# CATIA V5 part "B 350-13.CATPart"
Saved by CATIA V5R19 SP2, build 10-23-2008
Part number: B 350-13
Bounding box of the stored display mesh (mm): x -15.868 to 15.868, y -15.868 to 15.868, z 0 to 75.4
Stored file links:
  C:\Users\Bora\Desktop\3D Katı model\B serisi\B 350\B 350-13.CATPart
  C:\Program Files\Dassault Systemes\B19\intel_a\reffiles\standard\MetricThickPitch.txt
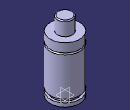
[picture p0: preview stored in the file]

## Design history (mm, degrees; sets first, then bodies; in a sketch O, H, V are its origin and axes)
Body1 (main body)
  Sketch1 on yz-plane, origin (0, 0, 0), H (0, 1, 0), V (0, 0, 1)
    point P3 (8, 74.4)
    point P5 (8, 74.4)
    point P7 (16, 50.9)
    point P8 (16, 48.9)
    point P12 (16, 48.9)
    point P13 (16, 50.9)
    line L1 (16, 0) -> (16, 4)
    line L2 (8, 74.4) -> (8, 60.4)
    arc A1 centre (7, 74.4) radius 1 from (8, 74.4) to (7, 75.4) ccw
    arc A2 centre (16, 49.9) radius 1 from (16, 50.9) to (16, 48.9) ccw
    line L3 (13.5, 7.5) -> (13.5, 4)
    line L4 (16, 7.5) -> (16, 48.9)
    line L5 (16, 50.9) -> (16, 60.4)
    line L6 (7, 75.4) -> (0, 75.4)
    point P15 (0, 75.4)
    line L7 (8, 60.4) -> (16, 60.4)
    line L8 (0, 0) -> (16, 0)
    line L9 (13.5, 7.5) -> (16, 7.5)
    line L10 (13.5, 4) -> (16, 4)
    coincidence: P15 V, P3 P5, P7 P13, P8 P12
    tangency: L6 A1
    horizontal: L7 H, L8 H, L9 H, L10 H
  Shaft1: profile Sketch1, axis Sketch1.V, angle 360
  Sketch2 on face of Shaft1 from Sketch1.L8, origin (0, 0, 0), H (1, 0, 0), V (0, -1, 0)
    point P1 (0, 0)
  Hole1: placed by Sketch2, at (0, 0, 0) direction (0, 0, 1), diameter 6.647, depth 7, threaded "M8", thread diameter 8, thread depth 7, pitch 1.25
